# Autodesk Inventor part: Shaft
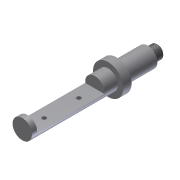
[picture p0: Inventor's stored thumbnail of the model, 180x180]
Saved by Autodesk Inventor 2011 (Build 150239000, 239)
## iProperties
Shininess: 77.0
Length Units: 11269
Angle Units: 11279
Time Units: 11290
Mass Units: 11283
Length Display Precision: 3
Angle Display Precision: 2
Created: 2002-01
Part Number: Shaft
Document SubType Name: Modeling
Designer: ***
Density: 1 g/cm^3
Density: 0.0
Volumn: 0.0
Area: 0.0
PropertySet Name: Model Information
Control State: 0
Master: False
Checked Out: False
Author: ***
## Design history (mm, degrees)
sketch "Sketch1"
  geometry: L1 (-0.547, 128.546)-(18.203, 128.546); L2 (18.203, 128.546)-(18.203, 99.646); L3 (18.203, 99.646)-(27.453, 99.646); L4 (27.453, 99.646)-(27.453, 9.846); L5 (27.453, 9.846)-(43.053, 9.846); L6 (43.053, 9.846)-(43.053, -14.154); L7 (43.053, -14.154)-(27.453, -14.154); L8 (27.453, -14.154)-(27.453, -261.254); L9 (27.453, -261.254)-(-0.547, -261.254); L10 (-0.547, -261.254)-(-0.547, 128.546)
  constraints: 20 end point, 8 parallel, 1 horizontal, 1 perpendicular
  dimensions: "d0" = 37.5 diameter of L2 L10; "d2" = 56 diameter of L4 L10; "d3" = 87.2 diameter of L6 L10; "d4" = 56 diameter of L8 L10; "d5" = 389.8 distance of L9.end L1.start; "d6" = 28.9 distance of L1.end L2.end; "d7" = 89.8 distance of L3.end L4.end; "d8" = 24 distance of L5.end L6.end
revolve "Revolution1" sketch "Sketch1" stored, may be unused: angle "d9" = 90 deg
sketch "Sketch2"
  geometry: L1 (-73.994, -52.354)-(71.576, -52.354); L2 (71.576, -52.354)-(71.576, -246.154); L3 (71.576, -246.154)-(-73.994, -246.154); L4 (-73.994, -246.154)-(-73.994, -52.354); L5 (-28.547, -261.254)-(27.453, -261.254) reference; L6 (-44.147, -14.154)-(43.053, -14.154) reference
  constraints: 8 end point, 2 parallel, 1 horizontal, 1 perpendicular
  dimensions: "d10" = 193.8 distance of L3.end L1.start; "d14" = 38.2 distance between parallel lines of L6 L1
extrude "Extrusion1" cut sketch "Sketch2" stored distance "d12" = 10; taper "d13" = 0 deg
extrude "Extrusion2" cut sketch "Sketch2" distance "d15" = 3.1; taper "d16" = 0 deg
sketch "Sketch3"
  geometry: L1 (27.281, -52.354)-(27.281, -246.154) reference; L2 (27.281, -52.354)-(-28.375, -52.354) reference; 2 further points
  dimensions: "d17" = 27.25 distance from line of L1 point (0.031, -99.254); "d18" = 0 horizontal distance of point (0.031, -99.254) point (0.031, -199.254); "d19" = 100 distance of point (0.031, -99.254) point (0.031, -199.254); "d20" = 46.9 distance from line of L2 point (0.031, -99.254)
hole "Hole1" sketch "Sketch3" at (0.031, -199.254), (0.031, -99.254) diameter "d21" = 12.5; stored, may be unused: countersink angle "d25" = 82 deg, drill point angle "d27" = 118 deg; dims "d22" = 6, "d23" = 4, "d24" = 2, "d26" = 8
chamfer "Chamfer1" distance "d28" = 3; stored, may be unused: second distance "d29" = 3, angle "d32" = 45 deg
thread "Thread1" dims "d30" = 10, "d31" = 0
body "Solid1"
